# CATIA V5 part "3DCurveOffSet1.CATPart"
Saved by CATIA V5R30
Part number: Part1
Bounding box of the stored display mesh (mm): x -47.659 to 151.901, y -137.348 to -39.765, z 0 to 40
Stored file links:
  D:\PROJECTS\CATIA V56R 2020\Resources\Parts File\c17_catia_v6_6r2020_prt\3DCurveOffSet1.CATPart
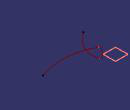
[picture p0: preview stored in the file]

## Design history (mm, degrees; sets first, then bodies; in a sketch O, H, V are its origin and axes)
Set1
  Sketch1 on xy-plane, origin (0, 0, 0), H (1, 0, 0), V (0, 1, 0)
    spline S1 through (-47.6585, -137.3483) (-29.3791, -10.2036) (-33.7949, 2.3216) (-29.4249, 29.9074)
  Plane1: type Offset, RefPlane xy-plane, Offset 20
  Sketch2 on Plane1, origin (0, 0, 20), H (1, 0, 0), V (0, 1, 0)
    spline S1 through (-28.771, 49.7054) (-11.6844, 72.6296) (11.4524, 88.4047) (30.8031, 89.9822) (65.2979, 82.489)
  Connect1: Curve1 Sketch1, Point1 vertex of Sketch1, Tension1 1, Curve2 Sketch2, Point2 vertex of Sketch2, Tension2 1
  Plane2: type Offset, RefPlane Plane1, Offset 20
  Sketch3 on Plane2, origin (0, 0, 40), H (1, 0, 0), V (0, 1, 0)
    spline S1 through (-172.8475, 33.6025) (-66.9858, 1.1425) (22.9569, -48.4801) (151.9012, -49.5994)
  Corner1 "Reference Curve": Element1 Sketch3, Element2 Connect1, Radius 10, Direction Plane2
Set2
  Point1: (0, 0, 0)
  Line1: type PtDir, RefPoint Point1, Direction xy-plane, Start 150, End 20
  Circle1: type CtrRad, Start 0, End 180, Center vertex of Line1, Support Plane2, Radius 80, FirstDirection (1, 0, 0)
Body1 (main body)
